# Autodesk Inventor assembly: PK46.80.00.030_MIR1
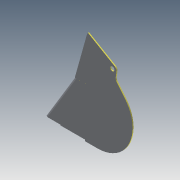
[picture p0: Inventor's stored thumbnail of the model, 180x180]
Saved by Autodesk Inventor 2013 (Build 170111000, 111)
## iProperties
Created: 2005-01
Part Number: PK46.80.00.030_MIR1
Document SubType Name: Assembly
Designer: hoeyj
Manufacturer: Standard
Standards Organization: Custom
Author: SAlex
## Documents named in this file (3)
- D:\FrontLoaderVault\Data\Assy, Chassis, Front\PK46.80.00.030_MIR1.iam
- D:\FrontLoaderVault\Data\Assy, Chassis, Front\PK46.80.00.017_MIR1.ipt
- D:\FrontLoaderVault\Data\Assy, Chassis, Front\PK46.80.00.019_MIR1.ipt
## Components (2 placed, 2 different names)
1. PK46.80.00.017_MIR1:1 — Mate:2, Flush:1, Mate:1
2. PK46.80.00.019_MIR1:1 — Mate:2, Flush:1, Mate:1
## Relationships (3: Mate 2, Flush 1)
- Mate:2: PK46.80.00.017_MIR1:1 ↔ PK46.80.00.019_MIR1:1
- Flush:1: PK46.80.00.017_MIR1:1 ↔ PK46.80.00.019_MIR1:1
- Mate:1: PK46.80.00.017_MIR1:1 ↔ PK46.80.00.019_MIR1:1
